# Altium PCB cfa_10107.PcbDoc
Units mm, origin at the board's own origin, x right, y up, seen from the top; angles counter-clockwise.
Board outline 25.5 x 29.1 mm, 2 copper layers (Top Layer, Bottom Layer); 16 components, 21 nets, 73 pads, 42 vias.
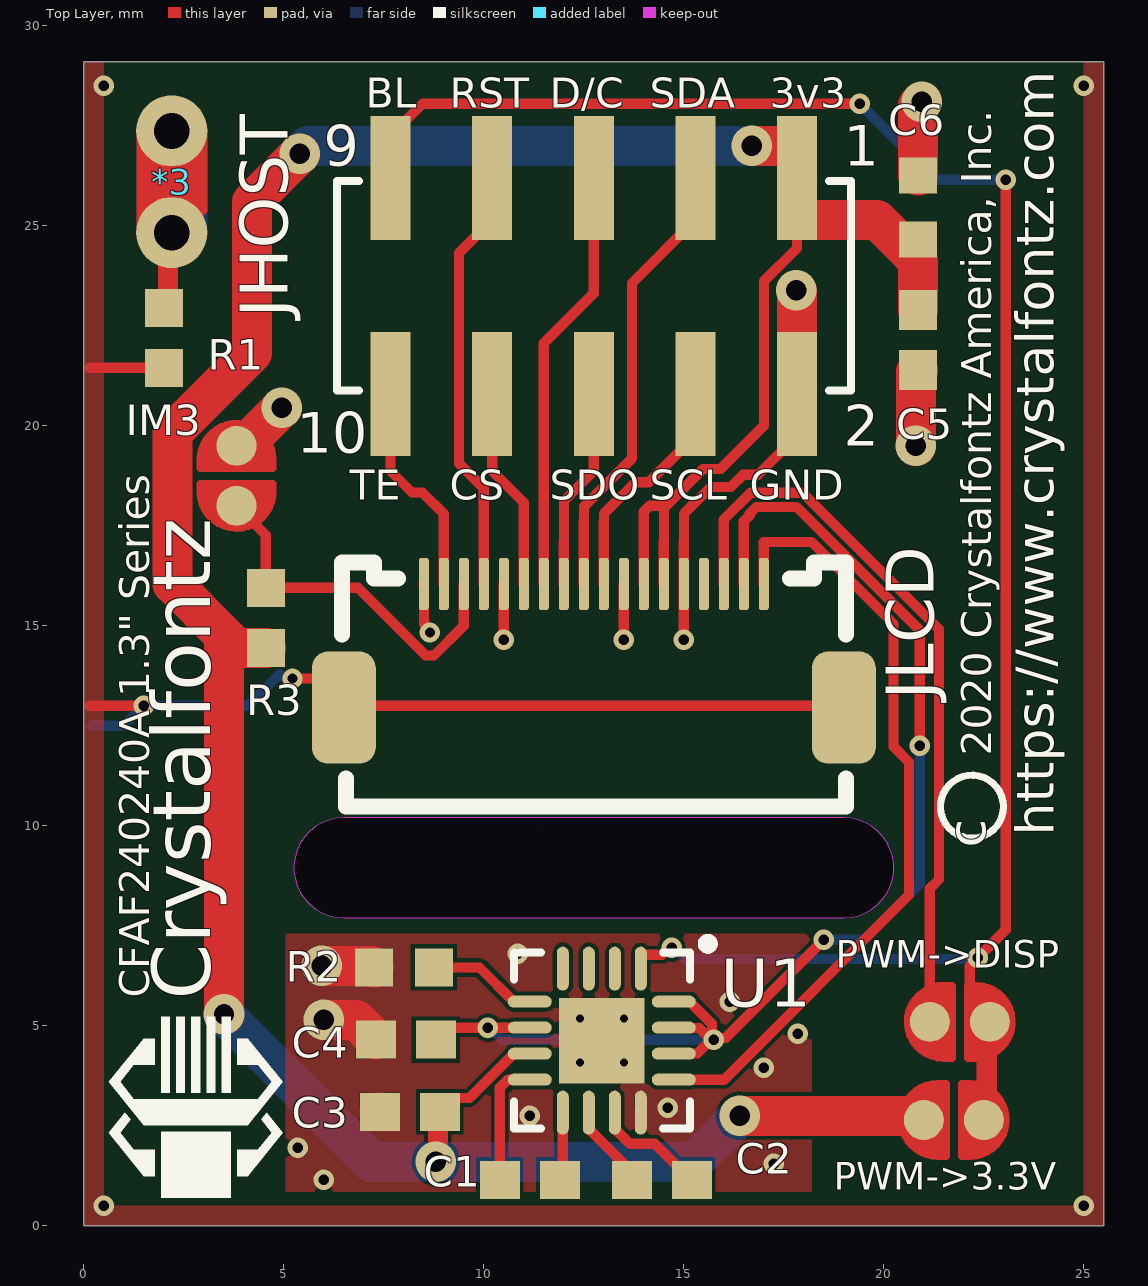
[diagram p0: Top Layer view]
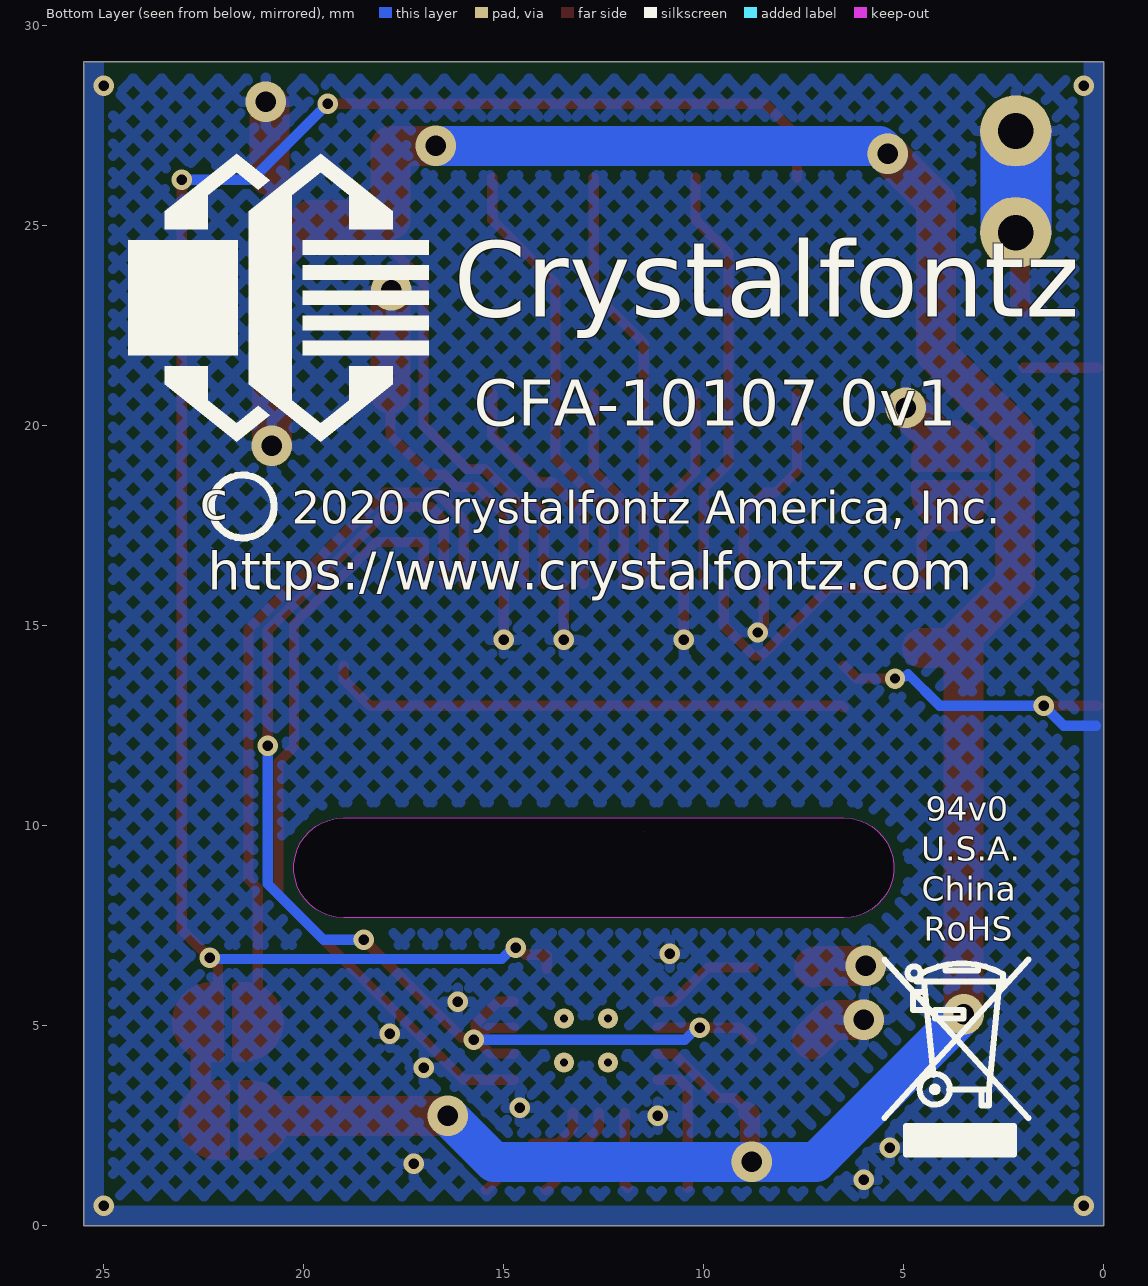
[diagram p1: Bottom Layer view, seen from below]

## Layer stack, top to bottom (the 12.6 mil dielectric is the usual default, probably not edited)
Top Solder: solder mask 0.0102, Solder Resist, Dk 3.5
Top Layer: signal copper 0.0356
Dielectric 2: dielectric 0.32, FR-4, Dk 4.8
Bottom Layer: signal copper 0.0356
Bottom Solder: solder mask 0.0102, Solder Resist, Dk 3.5

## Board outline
0,0 25.5,0 25.5,29.1 0,29.1
cut-out: 6.5,7.7 19,7.7 ccw(c19,8.95) 19,10.2 6.5,10.2 ccw(c6.5,8.95)
cut-out: 11.5,9.85

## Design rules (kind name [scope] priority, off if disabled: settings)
BoardOutlineClearance "Board Outline" [OnLayer('Board Outline')] p1: gap=0 ignorepadtopadclearanceinfootprint=FALSE
BoardOutlineClearance "Poly Design" [InNet('FG')] p2: gap=0 ignorepadtopadclearanceinfootprint=FALSE
BoardOutlineClearance [All] p3: gap=0.254 ignorepadtopadclearanceinfootprint=FALSE
Clearance Clearance_1 [InNamedPolygon('NONET_L01_P007')] p1: gap=0.254 ignorepadtopadclearanceinfootprint=FALSE except(0: Arc-Hole Track-Hole SMDPad-Hole THPad-Hole Via-Hole Fill-Hole Poly-Hole Region-Hole Text-Hole)
Clearance [All] p2: gap=0.1 ignorepadtopadclearanceinfootprint=TRUE
ComponentClearance [All] p1 off: gap=0.254 collisioncheckmode=3 verticalgap=0.254 showdistances=FALSE
MinimumSolderMaskSliver [All] p1: minsoldermaskwidth=0.1
PlaneConnect [InNet('FG')] p1: planeconnectstyle=Direct reliefexpansion=0.508 reliefentries=4 reliefconductorwidth=0.254 reliefairgap=0.254
PlaneConnect PlaneConnect_1 [All] p2: planeconnectstyle=Relief reliefexpansion=0.508 reliefentries=4 reliefconductorwidth=0.254 reliefairgap=0.254
PolygonConnect PolygonConnect_2 [All vs IsNamedPolygon('NONET_L01_P004')] p1: connectstyle=Direct reliefconductorwidth=0.254 reliefentries=4 polygonreliefangle="90 Angle" airgapwidth=0.254
RoutingVias [All] p1: holewidth=0.381 width=0.762 viastyle="Through Hole" minholewidth=0.254 minwidth=0.508 maxholewidth=0.508 maxwidth=1.016
SilkToSilkClearance [All] p1: silktosilkclearance=0.1
SilkToSolderMaskClearance [IsPad] p1: minsilkscreentomaskgap=0.1 clearancetoexposedcopper=TRUE
SolderMaskExpansion Vias [IsVia] p1: expansion=0.102 istentingtop=FALSE
SolderMaskExpansion [All] p2: expansion=0.102 istentingtop=FALSE
Width Power [InNetClass('PowerNets')] p1: maxlimit=1 minlimit=0.254 preferedwidth=0.5
Width [All] p2: maxlimit=0.254 minlimit=0.127 preferedwidth=0.152
25 further rules are at their usual default settings.

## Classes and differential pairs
net class PowerNets: 3V3 GND

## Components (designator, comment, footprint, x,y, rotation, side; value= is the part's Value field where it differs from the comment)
*3 "Scope contact .1\"" Scope_Contact 2.2,26.1 r90 top
C1 "CAP CER 1UF 25V X5R 0603" 00289_CAM 11.15,1.15 r180 top value=1uF
C2 "CAP CER 1UF 25V X5R 0603" 00289_CAM 14.45,1.15 r0 top value=1uF
C3 "CAP CER 1UF 25V X5R 0603" 00289_CAM 8.15,2.85 r180 top value=1uF
C4 "CAP CER 1UF 25V X5R 0603" 00289_CAM 8.05,4.654 r0 top value=1uF
C5 "CAP CER 1UF 25V X5R 0603" 00289_CAM 20.859,22.15 r270 top value=1uF
C6 "CAP CER 0.1UF 25V X7R 0603" 00133_CAM 20.859,25.454 r270 top value=0.1uF
IM3 "Jumper_Open" Jumper_7mil_gap_open#1 3.82,18.75 r0 top
JHOST "CONN HEADER SMD 10POS 2.54MM" 16118_CAM 12.75,23.5 r180 top
JLCD "CONN FPC BOTTOM 18POS 0.30MM R/A" CS050Z18G-A0_CAM 12.75,14.5 r180 top
PWM->3.3V "Jumper_Open" Jumper_7mil_gap_open#2 21.75,2.646 r90 top
PWM->DISP "Jumper_Open" Jumper_7mil_gap_open#3 21.9,5.1 r90 top (schematic designator PWM->DISP_PWM)
R1 "RES SMD 1M OHM 1% 1/10W 0603" 16110_CAM 2,22.2 r270 top value=1MΩ
R2 "RES SMD 4.02K OHM 1% 1/10W 0603" 16110_CAM 8,6.458 r0 top value=4.02kΩ
R3 "RES SMD 100K OHM 1% 1/10W 0603" 16110_CAM 4.55,15.2 r270 top value=100kΩ
U1 "IC LED DRIVER RGLTR DIM SOT23-6" 16099_CAM 12.95,4.628 r270 top value=N/A

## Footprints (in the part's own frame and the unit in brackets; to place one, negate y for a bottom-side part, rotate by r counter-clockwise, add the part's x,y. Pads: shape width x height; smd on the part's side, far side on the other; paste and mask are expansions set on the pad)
00133_CAM [mm] "Chip Capacitor, 2-Leads, Body 1.60x0.80mm, IPC Medium Density"
  rect 0.9x0.95 smd: 1(-0.8,0) 2(0.8,0)
  body extent -0.85,-0.45 0.85,0.45, height 0.9
00289_CAM [mm] "Chip Capacitor, 2-Leads, Body 1.60x0.80mm, IPC Medium Density"
  rect 1x0.95 smd: 1(-0.75,0) 2(0.75,0)
  body extent -0.85,-0.45 0.85,0.45, height 0.9
16099_CAM [mm] "QFN, 16-Leads, Body 4.00x4.00mm, Pitch 0.65mm, Thermal Pad 2.13x2.13mm, IPC Medium Density"
  oval 1.1x0.3 smd: 1(-1.8,0.975) 2(-1.8,0.325) 3(-1.8,-0.325) 4(-1.8,-0.975) 9(1.8,-0.975) 10(1.8,-0.325) 11(1.8,0.325) 12(1.8,0.975)
  oval 0.3x1.1 smd: 5(-0.975,-1.8) 6(-0.325,-1.8) 7(0.325,-1.8) 8(0.975,-1.8) 13(0.975,1.8) 14(0.325,1.8) 15(-0.325,1.8) 16(-0.975,1.8)
  rect 2.13x2.13 smd: 17(0,0)
  silkscreen extent -2.55,-2.2 2.2,2.77, body extent -2.04,-2.04 2.05,2.05, height 0.81
16110_CAM [mm] "Chip Resistor, 2-Leads, Body 1.60x0.85mm, IPC Medium Density"
  rect 0.95x0.95 smd: 1(-0.75,0) 2(0.75,0)
  body extent -0.88,-0.48 0.87,0.48, height 0.55
16118_CAM [mm] "Connector Header Surface Mount 12 position 0.100\" (2.54mm)"
  rect 1x3.1 smd: 1(-5.08,-2.7) 2(-5.08,2.7) 3(-2.54,-2.7) 4(-2.54,2.7) 5(0,-2.7) 6(0,2.7) 7(2.54,-2.7) 8(2.54,2.7) 9(5.08,-2.7) 10(5.08,2.7)
  silkscreen extent -6.43,-2.62 6.43,2.62, body extent -6.35,-3.75 6.35,3.75, height 9.62
CS050Z18G-A0_CAM [mm] "18 pin .05mm pitch connector"
  rrect50% 0.25x1.3 smd mask+0.05: 1(-4.25,-1.545) 2(-3.75,-1.545) 3(-3.25,-1.545) 4(-2.75,-1.545) 5(-2.25,-1.545) 6(-1.75,-1.545) 7(-1.25,-1.545) 8(-0.75,-1.545) 9(-0.25,-1.545) 10(0.25,-1.545) 11(0.75,-1.545) 12(1.25,-1.545) 13(1.75,-1.545) 14(2.25,-1.545) 15(2.75,-1.545) 16(3.25,-1.545) 17(3.75,-1.545) 18(4.25,-1.545)
  rrect50% 1.6x2.8 smd: FG1(-6.25,1.545) FG2(6.25,1.545)
  silkscreen extent -6.3,-2.08 6.3,4.02, body extent -6.55,-1.82 6.55,3.5, height 2.91
Jumper_7mil_gap_open#1 [mm]
  round 1 smd paste+0 mask+0: 1(0,0.75) 2(0,-0.75)
  Top Layer region: -0.9,0.2 -0.9,0.4 -0.811,0.79 -0.561,1.104 -0.2,1.277 0.2,1.277 0.561,1.104 0.811,0.79 0.9,0.4 0.9,0.4 0.9,0.2
  Top Layer region: -0.9,-0.2 -0.9,-0.4 -0.811,-0.79 -0.561,-1.104 -0.2,-1.277 0.2,-1.277 0.561,-1.104 0.811,-0.79 0.9,-0.4 0.9,-0.4 0.9,-0.2
  Top Layer lines w0.2: -0.9,-0.4 ccw(c0,-0.4) -0.002,-1.3 ccw(c0,-0.4) 0.437,-1.187 ccw(c0,-0.4) 0.9,-0.4 0.9,-0.2 -0.9,-0.2 -0.9,-0.4 ; -0.9,0.2 -0.9,0.4 cw(c0,0.4) 0.338,1.234 cw(c0,0.4) 0.543,1.117 cw(c0,0.4) 0.9,0.4 0.9,0.2 0,0.2 -0.9,0.2
Jumper_7mil_gap_open#2 [mm]
  round 1 smd paste+0 mask+0: 1(0,0.75) 2(0,-0.75)
  Top Layer region: -0.9,-0.2 -0.9,-0.4 -0.811,-0.79 -0.561,-1.104 -0.2,-1.277 0.2,-1.277 0.561,-1.104 0.811,-0.79 0.9,-0.4 0.9,-0.4 0.9,-0.2
  Top Layer region: -0.9,0.2 -0.9,0.4 -0.811,0.79 -0.561,1.104 -0.2,1.277 0.2,1.277 0.561,1.104 0.811,0.79 0.9,0.4 0.9,0.4 0.9,0.2
  Top Layer lines w0.2: 0,1.3 ccw(c0,0.4) -0.9,0.4 -0.9,0.2 0,0.2 0.9,0.2 0.9,0.4 ccw(c0,0.4) 0.104,1.294 ccw(c0,0.4) 0,1.3 ; -0.9,-0.2 0.9,-0.2 0.9,-0.4 cw(c0,-0.4) 0.793,-0.825 cw(c0,-0.4) -0.9,-0.4 -0.9,-0.2
Jumper_7mil_gap_open#3 [mm]
  round 1 smd paste+0 mask+0: 1(0,0.75) 2(0,-0.75)
  Top Layer region: -0.9,-0.2 -0.9,-0.4 -0.811,-0.79 -0.561,-1.104 -0.2,-1.277 0.2,-1.277 0.561,-1.104 0.811,-0.79 0.9,-0.4 0.9,-0.4 0.9,-0.2
  Top Layer region: -0.9,0.2 -0.9,0.4 -0.811,0.79 -0.561,1.104 -0.2,1.277 0.2,1.277 0.561,1.104 0.811,0.79 0.9,0.4 0.9,0.4 0.9,0.2
  Top Layer lines w0.2: 0.829,0.75 ccw(c0,0.4) -0.9,0.4 -0.9,0.2 0.9,0.2 0.9,0.4 ccw(c0,0.4) 0.829,0.75 ; -0.9,-0.2 0,-0.2 0.9,-0.2 0.9,-0.248 0.9,-0.4 cw(c0,-0.4) -0.857,-0.675 cw(c0,-0.4) -0.9,-0.4 -0.9,-0.2
Scope_Contact [mil]
  round 70 hole 35: 1(50,0) 2(-50,0)
  Top Layer region: -51,-31 50,-31 50,31 -51,31
  Top Layer lines w7.87: -51,-8.45 -51,3.94 -51,31 50,31 50,0 50,-31
  Bottom Layer region: -52,-31 49,-31 49,31 -52,31
  Bottom Layer lines w7.87: -52,31 49,31 49,0 49,-31 -52,-31 -52,31

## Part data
*3: library part Scope_Contact, "Dual pin .1\" spacing contact for scoping different lines. Through hole."
C1 C2 C3 C4 C5: library part 00289_SCH, "1µF ±10% 25V Ceramic Capacitor X5R 0603 (1608 Metric)", PACKAGE=0603
C6: library part 00133_SCH, "0.1µF ±10% 25V Ceramic Capacitor X7R 0603 (1608 Metric)", PACKAGE=0603
IM3 PWM->3.3V PWM->DISP: "Open jumper"
JHOST: library part 16118_SCH, "Connector Header Surface Mount 10 position 0.100\" (2.54mm)", PACKAGE=SMD
JLCD: library part CS050Z18G-A0, "18 Position FPC Connector Contacts, Top/Bottom, 0.50mm, Surface Mount, Right Angle", PACKAGE=SMD
R1: library part 00191_SCH, "1 MOhms ±1% 0.1W, 1/10W Chip Resistor 0603 (1608 Metric) Automotive AEC-Q200 Thick Film", PACKAGE=0603
R2: library part 03061_SCH, "4.02 kOhms ±1% 0.1W, 1/10W Chip Resistor 0603 (1608 Metric) Automotive AEC-Q200 Thick Film", PACKAGE=0603
R3: library part 00580_SCH, "100 kOhms ±1% 0.1W, 1/10W Chip Resistor 0603 (1608 Metric) Automotive AEC-Q200 Thick Film", PACKAGE=0603
U1: library part 16099_SCH, "LED Driver IC 1 Output DC DC Regulator Step-Up (Boost) PWM Dimming 550mA (Switch) SOT-23-6", PACKAGE=TQFN

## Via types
v1: diameter 0.508, hole 0.254, Top Layer to Bottom Layer, tented both sides, 25 vias
v2: diameter 1.016, hole 0.508, Top Layer to Bottom Layer, tented both sides, 11 vias
v3: diameter 0.5, hole 0.2, Top Layer to Bottom Layer, tented both sides, 4 vias
v4: diameter 0.508, hole 0.254, Top Layer to Bottom Layer, 2 vias

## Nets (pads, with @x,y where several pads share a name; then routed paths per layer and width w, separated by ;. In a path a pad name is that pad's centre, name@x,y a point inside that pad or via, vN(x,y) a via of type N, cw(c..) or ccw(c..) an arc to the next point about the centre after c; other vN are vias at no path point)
3V3: C3.1 C5.1 C6.2 JHOST.1 JLCD.6 JLCD.7 PWM->3.3V.1 R3.2 U1.7 | length 80.4
  Top Layer w0.254: C3.1 9.248,3.198 9.646,3.198 10.75,4.303 U1.7 ; JLCD.7 14,17.851 14.149,18 14.442,18 14.502,17.94 ; JLCD.6 14.5,17.095 14.502,17.097 14.502,17.94 ; JHOST.1@17.83,25.15 17.83,24.439 17.003,23.612 17.003,20.001 15.925,18.923 15.485,18.923 14.502,17.94
  Top Layer w0.5: v2(8.8,1.6) 8.85,1.65 8.85,2.8 C3.1
  Top Layer w1: v2(3.504,5.286) 3.504,14.762 ; R3.2 3.817,14.45 3.504,14.762 ; v2(5.4,26.8) 4.2,25.6 4.2,21.814 2.22,19.833 2.22,16.047 3.504,14.762 ; v2(16.4,2.75) 20.456,2.75 20.896,2.75 PWM->3.3V.1 ; v2(16.7,27) 17.83,27 JHOST.1 17.83,25.15 19.83,25.15 20.859,24.121 C5.1
  Bottom Layer w1: v2(3.504,5.286) 7.191,1.6 v2(8.8,1.6) 15.246,1.6 16.396,2.75 v2(16.4,2.75) ; v2(5.4,26.8) 5.404,26.8 5.604,27 v2(16.7,27)
BL_PWM: JHOST.9 PWM->3.3V.2 PWM->DISP.2 U1.1 | length 49.8
  Top Layer w0.254: JHOST.9 7.67,27.25 8.47,28.05 v4(19.4,28.05) ; U1.1 13.925,6.754 13.946,6.775 14.456,6.775 14.631,6.95 v1(14.7,6.95) ; PWM->3.3V.2 22.575,2.721 22.575,3.439 ; PWM->DISP.2 22.65,5.302 22.148,5.804 22.148,6 22.148,6.498 v1(22.35,6.7) 23.05,7.4 v4(23.05,26.15)
  Top Layer w0.508: 22.575,3.439 22.575,4.243
  Bottom Layer w0.254: v1(14.7,6.95) 14.769,6.95 15.05,6.669 22.319,6.669 v1(22.35,6.7) ; v4(19.4,28.05) 21.3,26.15 v4(23.05,26.15)
CS: JHOST.8 JLCD.13 | length 5.1
  Top Layer w0.254: JHOST.8 10.21,18.869 10.998,18.081 10.998,17.097 11,17.095 JLCD.13
D/C: JHOST.5 JLCD.12 | length 10.7
  Top Layer w0.254: JLCD.12 11.5,22.062 12.75,23.312 JHOST.5
DISP_PWM: JLCD.3 PWM->DISP.1 | length 18.6
  Top Layer w0.254: JLCD.3 16,17.655 16.671,18.326 17.967,18.326 21.381,14.912 21.381,8.657 21.15,8.426 21.15,5.929 PWM->DISP.1
EN: JLCD.4
FG: JLCD.FG1 JLCD.FG2 R1.2 | length 23.4
  Top Layer w0.254: 0.15,13 v1(1.5,13) ; 0.15,21.45 R1.2 ; v1(5.22,13.679) 6.179,13.679 JLCD.FG2@6.5,14 ; JLCD.FG2 6.545,13 18.348,13 19,13.652 JLCD.FG1@19,14.005
  Bottom Layer w0.254: 0.2,12.5 1,12.5 v1(1.5,13) 4.1,13 4.894,13.794 4.961,13.728 5.171,13.728 v1(5.22,13.679)
  other v1: 0.5,0.5 25,0.5 0.5,28.5 25,28.5
GND: *3.1 C3.2 C4.1 C5.2 C6.1 IM3.1 JHOST.2 JLCD.5 JLCD.8 JLCD.14 JLCD.18 R1.1 R2.1 U1.12 U1.17 | length 30
  Top Layer w0.2: 2.415,24.805 2.987,25.377 *3.1@2.987,27.37
  Top Layer w0.254: JLCD.18 8.502,16.043 8.502,15.051 8.652,14.901 v1(8.652,14.832) ; v1(10.5,14.65) JLCD.14 ; v1(13.5,14.65) JLCD.8 ; v1(15,14.65) 15,17.095 15.002,17.097 15.002,17.798 15.673,18.469 16.176,18.469 16.484,18.777 16.857,18.777 17.83,19.75 JHOST.2
  Top Layer w0.5: R1.1 2.1,23.05 2.1,24.805 2.1,27.27 *3.1
  Top Layer w1: IM3.1 3.996,19.5 4.363,19.867 4.946,20.45 v2(4.95,20.45) ; v2(5.95,6.5) 5.953,6.497 7.212,6.497 R2.1 ; v2(6,5.15) 6.003,5.147 6.807,5.147 C4.1 ; v2(17.815,23.385) 17.83,23.37 JHOST.2 ; v2(20.8,19.5) 20.8,21.341 C5.2 ; C6.1 20.853,26.26 20.853,28.003 v2(20.95,28.1)
  other v1: 6,1.15 17.25,1.55 5.35,1.95 11.15,2.75 14.6,2.95 17,3.95 17.85,4.8 16.15,5.6 10.85,6.8
IM3: IM3.2 JLCD.16 R3.1 | length 9.4
  Top Layer w0.254: IM3.2 4.257,17.563 4.55,17.27 R3.1 6.854,15.95 8.547,14.257 8.757,14.257 9.5,15 JLCD.16
LED_A: C4.2 JLCD.2 U1.6 U1.14 U1.15 U1.16 | length 32.5
  Top Layer w0.254: C4.2 9.098,4.953 10.1,4.953 U1.6 ; U1.14 14.759,4.311 15.343,4.311 v1@15.681,4.65 ; U1.15 14.759,4.944 15.388,4.944 v1@15.681,4.65 ; U1.16 15.15,5.603 15.701,5.051 15.701,4.67 v1@15.681,4.65 ; v1(15.75,4.65) 15.799,4.699 16.049,4.699 v1(18.5,7.15) ; JLCD.2 16.5,17.616 16.648,17.764 16.648,17.803 16.818,17.972 17.82,17.972 20.9,14.892 v1(20.9,12)
  Bottom Layer w0.254: v1(10.1,4.95) 10.169,4.95 10.469,4.65 v1(15.75,4.65) ; v1(18.5,7.15) 19.507,7.15 20.9,8.543 v1(20.9,12)
LED_K: JLCD.1 U1.13 | length 19.9
  Top Layer w0.254: U1.13 16.009,3.653 20.631,8.274 20.631,11.589 20.245,11.974 20.245,15.046 18.196,17.095 17,17.095 JLCD.1
NetC1_1: C1.1 U1.9 | length 1.9
  Top Layer w0.127: C1.1@11.75,1.177 C1.1@11.775,1.202
  Top Layer w0.254: C1.1@11.9,0.95 11.975,1.025 U1.9
NetC1_2: C1.2 U1.8 | length 3.3
  Top Layer w0.254: C1.2@10.4,0.95 10.4,3.45 10.603,3.653 U1.8
NetC2_1: C2.1 U1.10 | length 2.5
  Top Layer w0.254: U1.10 12.625,2.428 13.577,1.476 13.577,1.248 13.925,0.9 C2.1@13.95,0.9
NetC2_2: C2.2 U1.11 | length 3.2
  Top Layer w0.254: U1.11 13.275,2.428 13.652,2.051 14.274,2.051 15.425,0.9 C2.2@15.45,0.9
RST: JHOST.7 JLCD.15 | length 10.8
  Top Layer w0.254: JLCD.15 10,18.437 9.383,19.054 9.383,24.323 10.21,25.15 JHOST.7
SCL: JHOST.4 JLCD.9 | length 5.9
  Top Layer w0.254: JLCD.9 13,17.616 13.002,17.618 13.002,17.798 13.791,18.588 14.128,18.588 15.29,19.75 JHOST.4
SDA: JHOST.3 JLCD.10 | length 11.3
  Top Layer w0.254: JLCD.10 12.5,17.616 12.502,17.618 12.502,17.979 13.709,19.186 13.709,23.57 15.29,25.15 JHOST.3
SDO: JHOST.6 JLCD.11 | length 5.1
  Top Layer w0.254: JLCD.11 12,17.095 12.002,17.097 12.002,18.121 12.75,18.869 JHOST.6
TE: JHOST.10 JLCD.17 | length 5.5
  Top Layer w0.254: JHOST.10 7.67,18.869 8.205,18.334 8.463,18.334 8.998,17.798 8.998,17.097 9,17.095 JLCD.17
Vrset: R2.2 U1.5 | length 2.8
  Top Layer w0.254: R2.2 9.894,6.458 10.75,5.603 U1.5
pads on no net: *3.2 U1.2 U1.3 U1.4
copper on no net:
  other v3: 12.4,4.078 13.5,4.078 12.4,5.178 13.5,5.178

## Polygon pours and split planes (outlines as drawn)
GND on Top Layer "GND_L01_P002" (solid, pour order 2): 5.05,7.3 5.05,0.85 18.2,0.85 18.2,7.3
FG on Top Layer "FG_L01_P019" (solid, pour order 19): 0,29.1 0,0 25.5,0 25.5,29.1 25,29.1 25,0.5 0.5,0.5 0.5,29.1
GND on Bottom Layer "Top Layer-No Net" (hatched 45Degree grid 0.5 track 0.25, pour order 5): 0,0 25.5,0 25.5,29.1 0,29.1
FG on Bottom Layer "FG_L02_P004" (solid, pour order 4): 0,29.1 0,0 25.5,0 25.5,29.1 25,29.1 25,0.5 0.5,0.5 0.5,29.1
FG on Top Solder "FG_L01_P006" (solid): 0,29.1 0,0 25.5,0 25.5,29.1 25,29.1 25,0.5 16,0.5 16,0 9.5,0 9.5,0.5 0.5,0.5 0.5,29.1
FG on Bottom Solder "FG_L01_P006" (solid, pour order 6): 0,29.1 0,0 25.5,0 25.5,29.1 25,29.1 25,0.5 0.5,0.5 0.5,29.1
no net on Board Outline "NONET_L-01_P-001" (hatched Horizontal grid 0.508 track 0.203): 6.4,11.2

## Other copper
Top Layer:
  text ".GTL" at 46.25,-70.5 h1.65
  text "LAYER 1 (TOP Traces)" at -25.042,-70.541 h2.03
Bottom Layer:
  text ".GBL" at 46.25,-70.5 h1.65
  text "Board Outline" at -25.042,-70.541 h2.03
  text "LAYER 2 (BOTTOM Traces)" at -25.042,-70.541 h2.03

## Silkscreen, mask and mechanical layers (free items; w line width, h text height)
Top Overlay:
  circle w0.178: c22.205,10.478 r0.787
  region: 0.906,3.595 1.253,3.161 1.497,2.509 0.628,3.595
  region: 4.347,3.161 4.694,3.595 4.972,3.595 4.103,2.509
  region: 3.669,2.346 3.669,0.7 1.931,0.7 1.931,2.346
  region: 4.347,3.161 4.103,2.509 1.497,2.509 1.253,3.161
  region: 1.427,4.247 1.768,4.247 1.768,4.03 1.253,4.03
  region: 2.148,5.224 2.148,3.324 1.931,3.324 1.931,5.224
  region: 1.497,4.681 1.427,4.247 0.906,3.595 0.628,3.595
  region: 1.497,4.681 1.768,4.681 1.768,4.247 1.427,4.247
  region: 4.173,4.247 4.347,4.03 3.832,4.03 3.832,4.247
  region: 3.669,5.224 3.669,3.324 3.452,3.324 3.452,5.224
  region: 3.289,5.224 3.289,3.324 3.072,3.324 3.072,5.224
  region: 4.972,3.595 4.694,3.595 4.173,4.247 4.103,4.681
  region: 4.103,4.681 4.173,4.247 3.832,4.247 3.832,4.681
  region: 2.909,5.224 2.909,3.324 2.691,3.324 2.691,5.224
  region: 2.528,5.224 2.528,3.324 2.311,3.324 2.311,5.224
  region: 0.906,2.329 1.253,1.895 1.497,1.243 0.628,2.329
  region: 1.768,1.895 1.768,1.243 1.497,1.243 1.253,1.895
  region: 1.03,2.832 1.169,2.658 0.906,2.329 0.628,2.329
  region: 4.347,1.895 4.694,2.329 4.972,2.329 4.103,1.243
  region: 4.347,1.895 4.103,1.243 3.832,1.243 3.832,1.895
  region: 4.57,2.832 4.972,2.329 4.694,2.329 4.431,2.658
  text "BL" at 7.05,27.95 h0.75
  text "RST" at 9.15,27.95 h0.75
  text "D/C" at 11.65,27.95 h0.75
  text "SDA" at 14.15,27.95 h0.75
  text "3v3" at 17.15,27.95 h0.75
  text "TE" at 6.65,18.15 h0.75
  text "CS" at 9.15,18.15 h0.75
  text "SDO" at 11.65,18.15 h0.75
  text "SCL" at 14.15,18.15 h0.75
  text "GND" at 16.65,18.15 h0.75
  text "2020 Crystalfontz America, Inc." at 22.692,11.745 h0.75 r90
  text "https://www.crystalfontz.com" at 24.25,9.75 h0.95 r90
  text "c" at 22.55,9.45 h0.95 r90
  text "CFAF240240A 1.3\" Series" at 1.642,5.695 h0.75 r90
  text "Crystalfontz" at 3.65,5.65 h2.5 r90
  text ".GTO" at 46.25,-70.5 h1.65
  text "TOP Silk Screened Legend" at -25.042,-70.541 h2.03
Bottom Overlay:
  circle w0.15: c4.224,3.411 r0.382
  circle w0.15: c4.224,3.411 r0.069
  circle w0.15: c4.744,6.32 r0.165
  circle w0.178: c21.527,17.983 r0.787
  region: 24.388,24.64 21.65,24.64 21.65,21.76 24.388,21.76 24.388,24.64
  region: 20.03,22.12 16.88,22.12 16.88,21.76 20.03,21.76 20.03,22.12
  region: 22.398,24.91 23.478,24.91 23.478,25.36 21.678,26.8 20.845,26.134 21.133,25.903 21.678,26.339 22.398,25.763 22.398,24.91
  region: 17.78,24.91 17.78,25.36 19.58,26.8 21.38,25.36 21.38,21.04 19.58,19.6 17.78,21.04 17.78,21.49 18.86,21.49 18.86,20.637 19.58,20.061 20.3,20.637 20.3,25.763 19.58,26.339 18.86,25.763 18.86,24.91 17.78,24.91
  region: 20.03,24.01 16.88,24.01 16.88,23.65 20.03,23.65 20.03,24.01
  region: 20.03,24.64 16.88,24.64 16.88,24.28 20.03,24.28 20.03,24.64
  region: 20.03,22.75 16.88,22.75 16.88,22.39 20.03,22.39 20.03,22.75
  region: 22.398,21.49 23.478,21.49 23.478,21.04 21.678,19.6 20.845,20.266 21.133,20.497 21.678,20.061 22.398,20.637 22.398,21.49
  region: 20.03,23.38 16.88,23.38 16.88,23.02 20.03,23.02 20.03,23.38
  lines w0.15: 1.884,2.691 5.484,6.651 ; 1.884,6.651 5.484,2.691 ; 2.25,1.87 4.95,1.87 ; 2.25,1.96 4.95,1.96 ; 2.25,2.05 4.95,2.05 ; 2.25,2.14 4.95,2.14 ; 2.25,2.23 4.95,2.23 ; 2.25,2.32 4.95,2.32 ; 2.25,2.41 4.95,2.41 ; 2.426,6.11 4.682,6.11 ; 2.514,6.111 2.514,6.291 cw(c3.549,4.446) 4.585,6.291 4.584,6.111 ; 2.604,6.111 2.874,3.411 ; 3.054,3.411 3.054,3.007 2.874,3.007 2.874,3.411 ; 3.144,6.471 3.144,6.381 3.954,6.381 3.954,6.471 ; 3.864,3.411 2.874,3.411 ; 4.26,3.775 4.494,6.111 ; 4.494,5.391 4.764,5.391 4.764,5.841 4.494,5.841 ; 2.25,1.78 4.95,1.78 4.95,2.5 2.25,2.5 2.25,1.78 ; 3.504,5.182 4.224,5.182 4.224,5.391 3.504,5.391 3.504,5.182
  text "Crystalfontz" at 16.25,22.1 h3.25
  text "CFA-10107 0v1" at 15.75,20 h1.15
  text "c" at 22.6,17.65 h0.95
  text "2020 Crystalfontz America, Inc." at 20.3,17.55 h0.83
  text "https://www.crystalfontz.com" at 22.4,15.9 h0.95
  text "94v0" at 4.449,10.125 h0.6
  text "U.S.A." at 4.56,9.125 h0.6
  text "China" at 4.546,8.125 h0.6
  text "RoHS" at 4.496,7.125 h0.6
  text "BOTTOM Silk Screened Legend" at -25.042,-70.541 h2.03
  text ".GBO" at 46.261,-70.537 h1.65
Top Paste:
  text ".GTP" at 46.25,-70.5 h1.65
  text "TOP Paste Mask/Stencil" at -25.042,-70.541 h2.03
Bottom Paste:
  text ".GBP" at 46.25,-70.5 h1.65
  text "BOTTOM Paste Mask/Stencil" at -25.042,-70.541 h2.03
Top Solder:
  text ".GTS" at 46.25,-70.5 h1.65
  text "TOP Solder Resist Mask" at -25.042,-70.541 h2.03
Bottom Solder:
  text ".GBS" at 46.25,-70.5 h1.65
  text "BOTTOM Solder Resist Mask" at -25.042,-70.541 h2.03
Drill Guide:
  text ".GG1" at 46.25,-70.5 h1.65
  text "Drill Guide" at -25.042,-70.541 h2.03
Board Outline:
  lines w0.254: 0,0 25.5,0 25.5,29.1 0,29.1 0,0 ; 6.5,7.7 cw(c6.5,8.95) 6.5,10.2 19,10.2 cw(c19,8.95) 19,7.7 6.5,7.7
Top Assembly:
  text "TOP Assembly Drawing" at -25,-70.5 h2.03
  text ".GM2" at 46.218,-70.534 h1.65
Bottom Assembly:
  text "BOTTOM Assembly Drawing" at -25,-70.5 h2.03
  text ".GM3" at 46.25,-70.5 h1.65
ESD Copper:
  text "ESD Copper" at -25,-70.5 h2.03
  text ".GM4" at 46.25,-70.5 h1.65
Keepouts:
  text "Keepouts" at -25,-70.5 h2.03
  text ".GM13" at 46.25,-70.5 h1.65
Placement:
  text "Placement" at -25,-70.5 h2.03
  text ".GM15" at 46.25,-70.5 h1.65
Drill Drawing:
  lines w0.254: 27.2,-4.15 24.6,-0.9 ; 24.6,-0.9 25.85,-1.4 24.75,-2.1 24.6,-0.9 ; -31.111,66.389 -30,66.389 -30,67.5 -31.111,67.5 -31.111,66.389 ; -31.111,70 -30,70 -30.556,68.889 -31.111,70 ; -31.111,71.667 -30.833,71.667 -30.556,71.389 -30.278,71.667 -30,71.667 -30.278,71.944 -30,72.222 -30.278,72.222 -30.556,72.5 -30.833,72.222 -31.111,72.222 -30.833,71.944 -31.111,71.667 ; -31.111,73.889 -30.556,74.167 -30,73.889 -30.278,74.444 -30,75 -30.556,74.722 -31.111,75 -30.833,74.444 -31.111,73.889
  lines w0.381: -32.135,65.639 52.338,65.639 ; -32.135,75.639 52.338,75.639 ; -22.674,63.139 -22.674,78.139 ; -13.502,63.139 -13.502,78.139 ; 5.001,63.139 5.001,78.139 ; 13.712,63.139 13.712,78.139 ; 38.879,63.139 38.879,78.139 ; -32.135,63.139 52.338,63.139 52.338,78.139 -32.135,78.139 -32.135,63.139
  text "LAYERS: 2" at 90.849,88.899 h1.5
  text "MATERIAL: FR4, RoHS, 94v0" at 90.849,85.899 h1.5
  text "THICKNESS: 1.6mm (~62 mils)" at 90.849,82.899 h1.5
  text "FINISH: Gold (ENIG) RoHS" at 90.849,79.899 h1.5
  text "SILK SCREEN: White" at 90.849,76.899 h1.5
  text "Symbol" at -30.635,76.389 h1.2
  text "Count" at -21.924,76.389 h1.2
  text "Hole Size" at -12.752,76.389 h1.2
  text "Plated" at 5.751,76.389 h1.2
  text "Drill Layer Pair" at 14.462,76.389 h1.2
  text "Pad Shape" at 39.629,76.389 h1.2
  text "4" at -21.924,73.889 h1
  text "0.200mm (7.87mil)" at -12.752,73.889 h1
  text "PTH" at 5.751,73.889 h1
  text "Top Layer - Bottom Layer" at 14.462,73.889 h1
  text "Rounded" at 39.629,73.889 h1
  text "SOLDER MASK: GREEN" at 90.849,73.899 h1.5
  text "27" at -21.924,71.389 h1
  text "0.254mm (10.00mil)" at -12.752,71.389 h1
  text "PTH" at 5.751,71.389 h1
  text "Top Layer - Bottom Layer" at 14.462,71.389 h1
  text "Rounded" at 39.629,71.389 h1
  text "11" at -21.924,68.889 h1
  text "0.508mm (20.00mil)" at -12.752,68.889 h1
  text "PTH" at 5.751,68.889 h1
  text "Top Layer - Bottom Layer" at 14.462,68.889 h1
  text "Rounded" at 39.629,68.889 h1
  text ">> IMPORTANT FABRICATION NOTES <<" at 91.099,67.649 h2
  text "2" at -21.924,66.389 h1
  text "0.889mm (35.00mil)" at -12.752,66.389 h1
  text "PTH" at 5.751,66.389 h1
  text "Top Layer - Bottom Layer" at 14.462,66.389 h1
  text "Rounded" at 39.629,66.389 h1
  text "44 Total" at -21.924,63.889 h1
  text "1) Many pads have intentional undersize solder mask" at 91.099,63.649 h1.25
  text "openings/oversize pads for physical strength." at 94.099,60.649 h1.25
  text "2) Make top and bottom solder masks exactly as" at 91.099,57.649 h1.25
  text "shown. Do _NOT_ \"open-up\" the solder mask layers." at 94.099,54.649 h1.25
  text "This design uses \"solder-mask-defined-pads\"." at 94.099,51.649 h1.25
  text "3) Silkscreened Legend (white) must be clean and" at 91.099,48.649 h1.25
  text "clear. Silkscreen legend must have good registration." at 94.099,45.649 h1.25
  text "Silkscreen is intentionally placed over bare copper." at 94.099,42.649 h1.25
  text "Do not clip silkscreen to solder mask layer." at 94.099,39.649 h1.25
  text "4) Board must be exactly like:" at 91.349,36.899 h1.25
  text "N/A" at 119,36.75 h1.25
  text "Copper should extend all the way to the edge of the board. It is not required that the board edge is plated. See \"PCB_Edge_Detail.pdf\" for more details." at 27.574,-13.2 h1.25
  text ".GD1" at 46.25,-70.5 h1.65
  text "Drill Drawing/Notes" at -25.042,-70.541 h2.03
Template:
  circle w0.203: c-48.651,100.399 r2.032
  circle w0.203: c-48.651,100.399 r1.016
  circle w0.203: c-48.651,-79.601 r2.032
  circle w0.203: c-48.651,-79.601 r1.016
  circle w0.254: c-16.84,-63.175 r0.925
  circle w0.203: c181.349,100.399 r1.437
  circle w0.203: c181.349,100.399 r0.718
  circle w0.203: c181.349,-79.601 r2.032
  circle w0.203: c181.349,-79.601 r1.016
  region: -22.553,-55.672 -19.141,-55.672 -19.141,-56.062 -22.553,-56.062 -22.553,-55.672
  region: -20.116,-54.015 -20.116,-53.528 -22.066,-51.969 -24.015,-53.528 -24.015,-58.207 -22.066,-59.766 -20.116,-58.207 -20.116,-57.719 -21.286,-57.719 -21.286,-58.643 -22.066,-59.267 -22.845,-58.643 -22.845,-53.092 -22.066,-52.468 -21.286,-53.092 -21.286,-54.015 -20.116,-54.015
  region: -25.117,-54.015 -26.287,-54.015 -26.287,-53.528 -24.337,-51.969 -23.436,-52.69 -23.748,-52.94 -24.337,-52.468 -25.117,-53.092 -25.117,-54.015
  region: -22.553,-54.99 -19.141,-54.99 -19.141,-55.38 -22.553,-55.38 -22.553,-54.99
  region: -22.553,-54.308 -19.141,-54.308 -19.141,-54.698 -22.553,-54.698 -22.553,-54.308
  region: -22.553,-57.037 -19.141,-57.037 -19.141,-57.427 -22.553,-57.427 -22.553,-57.037
  region: -22.553,-56.355 -19.141,-56.355 -19.141,-56.745 -22.553,-56.745 -22.553,-56.355
  region: -27.272,-54.308 -24.307,-54.308 -24.307,-57.427 -27.272,-57.427 -27.272,-54.308
  region: -25.117,-57.719 -26.287,-57.719 -26.287,-58.207 -24.337,-59.766 -23.436,-59.045 -23.748,-58.795 -24.337,-59.267 -25.117,-58.643 -25.117,-57.719
  lines w0.102: -51.699,-79.601 -45.603,-79.601 ; -51.699,100.399 -45.603,100.399 ; -48.651,-82.649 -48.651,-76.553 ; -48.651,97.351 -48.651,103.447 ; 178.301,-79.601 184.397,-79.601 ; 179.194,98.244 183.504,102.554 ; 179.194,102.554 183.504,98.244 ; 181.349,-82.649 181.349,-76.553
  lines w0.254: -27.762,-63.557 ccw(c-26.778,-63.588) -26.745,-64.572 ; -27.762,-63.556 -27.762,-52.634 ; -27.762,-52.635 cw(c-26.778,-52.602) -26.747,-51.618 ; -26.873,-71.557 26.213,-71.557 ccw(c26.213,-70.541) 27.229,-70.541 27.229,-66.604 ccw(c26.213,-66.604) 26.213,-65.588 -26.873,-65.588 ccw(c-26.778,-66.568) -27.762,-66.604 -27.762,-70.541 ccw(c-26.778,-70.577) -26.873,-71.557 ; -26.746,-64.572 12.497,-64.572 ccw(c12.497,-63.556) 13.513,-63.556 13.513,-52.634 ccw(c12.497,-52.634) 12.497,-51.618 -26.746,-51.618 ; 14.656,-56.572 ccw(c15.64,-56.603) 15.673,-57.587 ; 14.656,-56.571 14.656,-52.634 ; 14.656,-52.635 cw(c15.64,-52.602) 15.671,-51.618 ; 15.672,-57.587 66.726,-57.587 ccw(c66.726,-56.571) 67.742,-56.571 67.742,-52.634 ccw(c66.726,-52.634) 66.726,-51.618 15.672,-51.618 ; 28.245,-70.542 ccw(c29.229,-70.573) 29.262,-71.557 ; 28.245,-70.541 28.245,-66.604 cw(c29.23,-66.573) 29.261,-65.588 66.853,-65.588 cw(c66.853,-66.604) 67.869,-66.604 67.869,-70.541 cw(c66.853,-70.541) 66.853,-71.557 29.261,-71.557 ; 45.245,-63.557 ccw(c46.229,-63.588) 46.262,-64.572 ; 45.245,-63.556 45.245,-59.619 ; 45.245,-59.62 cw(c46.229,-59.587) 46.26,-58.603 ; 46.261,-64.572 66.853,-64.572 ccw(c66.853,-63.556) 67.869,-63.556 67.869,-59.619 ccw(c66.853,-59.619) 66.853,-58.603 46.261,-58.603 ; 14.783,-63.556 ccw(c15.799,-63.556) 15.799,-64.572 43.213,-64.572 ccw(c43.213,-63.556) 44.229,-63.556 44.229,-59.619 ccw(c43.213,-59.619) 43.213,-58.603 15.799,-58.603 ccw(c15.799,-59.619) 14.783,-59.619 14.783,-63.556
  lines w0.508: -28.778,-70.541 -28.778,-52.507 ; -28.778,-70.54 ccw(c-26.778,-70.575) -26.876,-72.573 ; -28.778,-52.509 cw(c-26.78,-52.6) -26.875,-50.602 ; -26.873,-72.573 66.853,-72.573 ccw(c66.853,-70.541) 68.885,-70.541 68.885,-52.507 ; -26.873,-50.602 66.853,-50.602 ; 66.855,-50.602 cw(c66.887,-52.602) 68.885,-52.508
  text "PROJECT" at 15.418,-52.939 h0.89
  text "VERSION" at 50.418,-52.939 h0.89
  text "Crystalfontz" at -18.999,-55.061 h4.57
  text "CFA-10107" at 23.2,-56.05 h3
  text "0v1" at 59.51,-56.109 h3
  text "12412 East Saltese Avenue" at -18.745,-57.327 h2.29
  text "Spokane Valley, WA 99216 USA" at -18.745,-59.435 h2.29
  text "PCB" at 15.545,-59.924 h0.89
  text "REVISION" at 34.545,-59.924 h0.89
  text "DATE" at 46.134,-59.924 h0.89
  text "Tel: (509) 892-1200 http://www.crystalfontz.com" at -27.127,-61.52 h2.11
  text "2020-03-03" at 48.676,-63.429 h2
  text "PCB10107" at 18.816,-63.683 h2
  text "0v1" at 37.614,-63.683 h2
  text "Copyright  c  2019 Crystalfontz America, Inc." at -27.254,-63.753 h2.29
  text "LAYER" at -26.873,-66.909 h0.89
  text "FILE NAME" at 29.134,-66.909 h0.89
  text "CFA10102_0v1" at 29.75,-70.25 h1.6

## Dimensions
6.5,7.7 to 6.5,10.2 on Board Outline
0,0 to 6.5,7.7 on Board Outline
0,0 to 5.25,8.95 on Board Outline
5.25,8.95 to 20.25,8.95 on Board Outline
25.5,29.1 to 25.5,0 on Board Outline
0,29.1 to 25.5,29.1 on Board Outline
